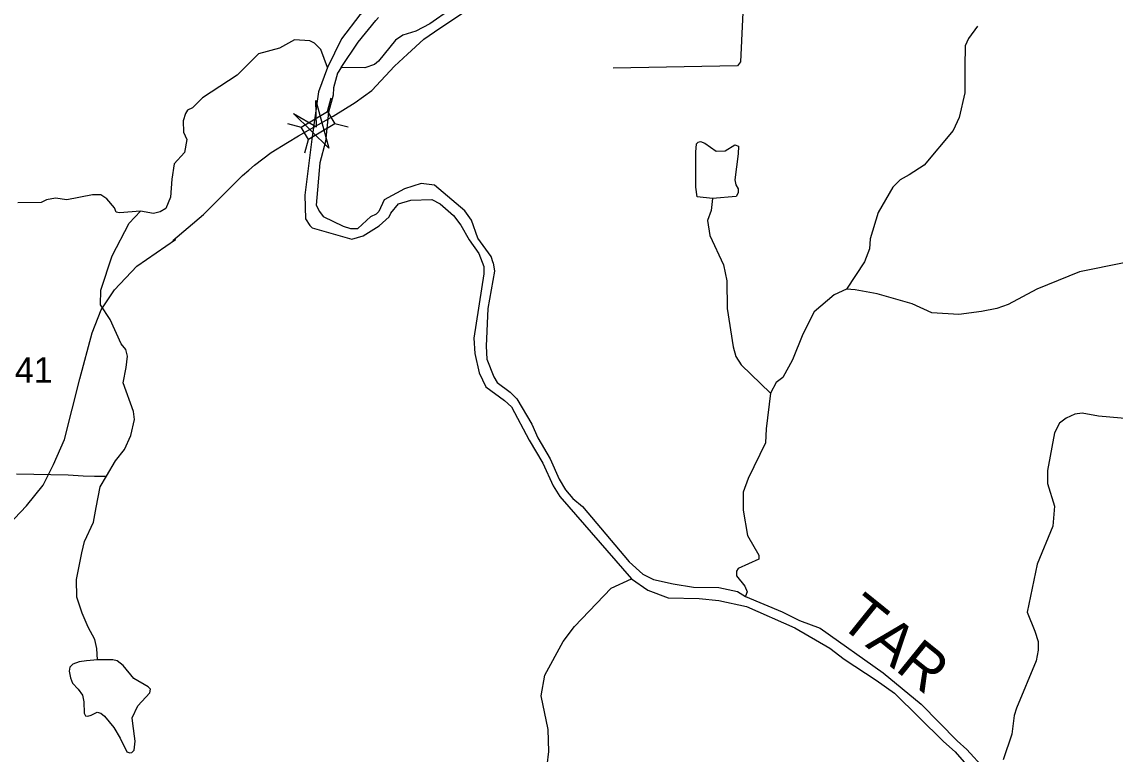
# Model space of a CAD drawing. Extents: x 2056842 to 2160602, y 826753 to 1016856.
# Drawn here: x 2071991 to 2077365, y 928971 to 932569 of the extents above; entities that cross this region are included whole.
import ezdxf

# ---------------------------------------------------------------- set-up
doc = ezdxf.new("R2010")
doc.units = 0
for name, color, linetype in [('Exist Hydrographic Creek Single Shore', 7, 'Continuous'), ('Exist Hydrographic Misc Water Feature', 7, 'Continuous'), ('Exist Hydrographic River Shore', 7, 'Continuous'), ('Exist Hydrographic River Shore Label', 7, 'Continuous'), ('Exist Road Non-System Type 51', 7, 'Continuous'), ('Exist Road Secondary Structure Standard Bridge Attributed CELL', 7, 'Continuous'), ('Exist Road Secondary Structure Standard Bridge CELL', 7, 'Continuous'), ('Exist Road Secondary Type 51 Attributed', 7, 'Continuous'), ('Exist Road Secondary Type 51 Number Label', 7, 'Continuous')]:
    doc.layers.add(name, color=color, linetype=linetype)

msp = doc.modelspace()

# ---------------------------------------------------------------- linework, layer by layer
at = {"layer": 'Exist Hydrographic Creek Single Shore'}
for points in [[(2074401.8, 933902.8), (2074378, 933806.8), (2074366.8, 933574.9), (2074351, 933482.8), (2074345.4, 933390.7), (2074302, 933218.6), (2074272, 933140.5), (2074220.3, 933052.4), (2074200.5, 933000.3), (2074185.1, 932856.3), (2074169.3, 932744.2), (2074139.6, 932676.1), (2074099.8, 932632), (2073996, 932559.7), (2073927.9, 932523.5), (2073864.2, 932503.3), (2073828.3, 932479.2), (2073744.4, 932376.9)], [(2073493.2, 932345.2), (2073461.1, 932432.8), (2073428.9, 932465), (2073406.8, 932476.9), (2073330.8, 932480.8), (2073257.1, 932440.7), (2073155.1, 932412.3), (2073049.3, 932308.1), (2072879.6, 932195.8), (2072829.4, 932147.7), (2072805.5, 932135.7), (2072795.7, 932119.8), (2072783.8, 932083.6), (2072785.9, 932027.8), (2072801.9, 931991.7), (2072790, 931927.6), (2072740, 931871.6), (2072728.2, 931795.7), (2072722.5, 931707.5), (2072698.4, 931651.6), (2072670.5, 931635.4), (2072638.5, 931627.6), (2072574.4, 931639.4)], [(2073744.4, 932376.9), (2073724.5, 932359.2), (2073677, 932344), (2073561.3, 932345.3)], [(2072574.4, 931639.4), (2072470.5, 931631.1), (2072454.5, 931635), (2072446.4, 931655.2), (2072408.3, 931699), (2072378.5, 931718.9), (2072338.5, 931718.8), (2072212.3, 931694.8), (2072156.3, 931702.5), (2072112.5, 931694.6), (2072086.4, 931682.3), (2071970.5, 931680.1)], [(2072406.9, 930337.2), (2072451.6, 930412.8), (2072494.8, 930467.4), (2072526.8, 930537.4), (2072544.5, 930615.4), (2072540.6, 930655.4), (2072488.3, 930795.4), (2072504.1, 930871.4), (2072510, 930927.3), (2072501.8, 930959.4), (2072479.9, 930987.3), (2072425.7, 931107.3), (2072377.5, 931179.1), (2072379.4, 931251.1), (2072435.2, 931419.3), (2072518.8, 931579.4), (2072574.6, 931639.5)], [(2071965.5, 930348.8), (2072219.2, 930342.8), (2072291.7, 930338.5), (2072348, 930337.2), (2072406.9, 930337.2)], [(2072362.1, 929434.2), (2072359.5, 929490.5), (2072349.3, 929534), (2072317.3, 929595.4), (2072287.9, 929663.3), (2072261, 929742), (2072259.8, 929829.1), (2072285.3, 929959.6), (2072299.4, 930015.9), (2072342.9, 930110.7), (2072357, 930182.4), (2072376.2, 930284.8), (2072406.9, 930337.2)]]:
    msp.add_lwpolyline(points, dxfattribs=at)
at = {"layer": 'Exist Hydrographic Misc Water Feature'}
for points in [[(2076687.9, 932548.2), (2076644.1, 932488), (2076628.1, 932452), (2076626.4, 932347.9), (2076626.8, 932220), (2076599.2, 932099.9), (2076569.4, 932035.7), (2076426.1, 931865.3), (2076352.1, 931817.2), (2076308.2, 931793), (2076272.3, 931756.9), (2076200.7, 931632.6), (2076161.2, 931502.5), (2076157.3, 931454.5), (2076133.5, 931390.4), (2076043.9, 931256.1)], [(2075303.8, 931929.8), (2075307.7, 931969.8), (2075315.7, 931977.8), (2075327.6, 931981.9), (2075347.7, 931973.9), (2075403.9, 931934.1), (2075447.8, 931936.3), (2075495.8, 931964.4), (2075513.8, 931958.5), (2075512, 931920.5)], [(2075386.5, 931702.1), (2075310.4, 931709.8), (2075304.5, 931757.8), (2075303.8, 931929.8)], [(2075512, 931920.5), (2075496.2, 931792.4), (2075500.3, 931768.5), (2075512.4, 931748.5), (2075512.6, 931728.5), (2075502.5, 931710.4), (2075386.5, 931702.1)], [(2075386.5, 931702.1), (2075378.7, 931642), (2075360.8, 931594), (2075373.1, 931520), (2075439.6, 931376.2), (2075455.8, 931296.3), (2075458.2, 931160.4), (2075486.9, 930972.4), (2075501.1, 930924.5), (2075527.1, 930884.6), (2075671.5, 930745)], [(2077575, 931521), (2077513.3, 931442.7), (2077473.3, 931410.6), (2077409.3, 931384.5), (2077189.7, 931341.7), (2076979.9, 931255.1), (2076840.1, 931180.7), (2076784.1, 931160.5), (2076708.2, 931146.2), (2076596.3, 931132), (2076464.2, 931139.5), (2076368.1, 931183.1), (2076196, 931232.7), (2076088, 931252.3), (2076043.9, 931256.1)], [(2076043.9, 931256.1), (2075984, 931227.9), (2075886.2, 931143.7), (2075830.6, 931035.5), (2075778.9, 930909.4), (2075731.2, 930821.2), (2075699.4, 930797.1), (2075671.5, 930745)], [(2075671.5, 930745), (2075650.2, 930569), (2075646.3, 930500.9), (2075561, 930324.7), (2075537, 930258.6), (2075537.4, 930170.6), (2075557.7, 930044.7), (2075614.1, 929948.9), (2075614.1, 929928.9), (2075512.2, 929882.6), (2075504.2, 929870.5), (2075504.4, 929846.5), (2075544.6, 929796.7), (2075556.7, 929768.7), (2075548.7, 929746.6)], [(2077579.9, 930605), (2077283.8, 930632.2), (2077203.6, 930645.9), (2077167.8, 930641.8), (2077123.9, 930621.6), (2077091.9, 930597.5), (2077067.9, 930549.4), (2077032.6, 930365.3), (2077032.8, 930301.3), (2077067.1, 930189.5), (2077059.5, 930091.4), (2076982.2, 929905.1), (2076932.8, 929669), (2076971.1, 929575.2), (2076987.3, 929525.2), (2076987.3, 929481.2), (2076977.7, 929429.1), (2076880.3, 929196.9), (2076868.4, 929160.8), (2076856.7, 929068.8), (2076815.1, 928942.7)], [(2074496.1, 928667.5), (2074523.8, 928731.5), (2074533.7, 928785.5), (2074573.4, 928915.7), (2074581.2, 928983.6), (2074578.8, 929091.6), (2074544.3, 929257.6), (2074562, 929359.6), (2074651.4, 929523.9), (2074707.1, 929598), (2074888.6, 929786.6), (2074988.5, 929832.9)], [(2072362.1, 929434.2), (2072309.5, 929429), (2072272.4, 929423.9), (2072241.7, 929412.4), (2072227.6, 929398.3), (2072223.8, 929379.1), (2072230.2, 929345.8), (2072240.4, 929319), (2072267.3, 929289.5), (2072289.1, 929260.1), (2072295.4, 929228.1), (2072296.7, 929173), (2072303.1, 929158.9), (2072314.6, 929157.7), (2072332.5, 929162.8), (2072362, 929176.9), (2072379.9, 929173), (2072397.8, 929157.7), (2072443.8, 929101.3), (2072474.5, 929048.9), (2072506.5, 928982.3), (2072521.9, 928977.2), (2072532.1, 928979.7), (2072543.6, 928991.3), (2072547.5, 929034.8), (2072536, 929121.8), (2072533.4, 929148.7), (2072561.5, 929207.6), (2072620.4, 929272.9), (2072624.2, 929290.8), (2072611.4, 929301), (2072542.3, 929343.3), (2072488.6, 929406), (2072459.2, 929430.3), (2072438.7, 929434.2), (2072362.1, 929434.2)]]:
    msp.add_lwpolyline(points, dxfattribs=at)
at = {"layer": 'Exist Hydrographic River Shore'}
for points in [[(2073743.6, 932682.9), (2073705.7, 932655.9), (2073680, 932621.2), (2073652.6, 932603.7), (2073562.9, 932485.3), (2073493.2, 932345.2)], [(2073561.3, 932345.1), (2073644.9, 932469.4), (2073731.5, 932576), (2073744.9, 932590.4)], [(2073493.2, 932345.2), (2073449.6, 932225.1), (2073415.9, 931993), (2073382.5, 931717), (2073384.6, 931600.9), (2073406.7, 931569), (2073418.8, 931557), (2073612.8, 931501.4), (2073669, 931517.5), (2073747.1, 931567)], [(2073561.3, 932345.1), (2073543.3, 932316.9), (2073523.4, 932245.2), (2073521.4, 932209.1), (2073497.7, 932124.9), (2073483.8, 931980.8), (2073456.1, 931877.1), (2073438.3, 931669.1), (2073454.4, 931636.9), (2073472.6, 931612.9), (2073570.7, 931565.3), (2073606.6, 931553.4), (2073642.6, 931553.3), (2073706.6, 931613.3), (2073734.4, 931625.5), (2073746.4, 931637.4)], [(2074307.6, 931384.6), (2074297.4, 931416.6), (2074233, 931506.2), (2074200.7, 931594.2), (2074168.8, 931640.1), (2074020.2, 931767.6), (2073954.4, 931775.5), (2073872.5, 931749), (2073772.6, 931695), (2073746.4, 931637.4)], [(2073747.1, 931567), (2073796.9, 931611.1), (2073804.9, 931629.1), (2073842.8, 931675.3), (2073902.7, 931693.4), (2074006.7, 931695.8), (2074046.7, 931675.9), (2074112.9, 931618.1), (2074149, 931570.2), (2074189.2, 931498.3), (2074237.6, 931430.4), (2074261.6, 931366.6), (2074261.8, 931330.6)], [(2074307.6, 931384.6), (2074313.6, 931344.4), (2074282.2, 931160.3), (2074272.8, 930976.5), (2074276.8, 930912.4), (2074311, 930824.7), (2074327.2, 930796.5), (2074391.5, 930748.9), (2074423.7, 930717.1), (2074497.9, 930593.1), (2074528, 930525.2), (2074588.5, 930421.6), (2074632.7, 930321.6), (2074662.8, 930269.8), (2074699, 930227.7), (2074747, 930188), (2074976, 929916.8), (2075044.3, 929855), (2075096.3, 929829), (2075192.3, 929807.3), (2075292.4, 929791.7), (2075416.4, 929790.2), (2075508.5, 929770.5), (2075548.4, 929746.4)], [(2074261.8, 931330.6), (2074212.8, 931014.4), (2074217.1, 930940.5), (2074239.2, 930844.5), (2074271.4, 930776.6), (2074363.7, 930708.9), (2074397.9, 930677.1), (2074484.5, 930513.2), (2074552.5, 930401.5), (2074603, 930289.7), (2074635.2, 930237.7), (2074988.5, 929832.9)], [(2074988.5, 929832.9), (2075068.6, 929777.2), (2075168.7, 929739.5), (2075320.7, 929736), (2075416.8, 929726.2), (2075553, 929696.7), (2075791, 929591.4), (2075963.3, 929492), (2076033.6, 929438.2), (2076189.9, 929334.7), (2076280.1, 929271), (2076520.8, 929033.8), (2076579.1, 928982), (2076635.2, 928918.1), (2076763.6, 928806.6), (2076881.7, 928740.9), (2076909.8, 928733.1)], [(2075548.4, 929746.4), (2075728.6, 929671.1), (2075813, 929627.4), (2075914.9, 929589.8), (2076225.7, 929370.8), (2076412.2, 929217.3), (2076588.6, 929035.8), (2076636.9, 928994.1), (2076723.2, 928898.1), (2076767.3, 928858.5)]]:
    msp.add_lwpolyline(points, dxfattribs=at)
at = {"layer": 'Exist Road Non-System Type 51'}
msp.add_lwpolyline([(2075554.8, 933033.2), (2075522.9, 932373.2), (2075508.8, 932353.1), (2074896.9, 932341.2)], dxfattribs=at)
at = {"layer": 'Exist Road Secondary Structure Standard Bridge Attributed CELL'}
msp.add_lwpolyline([(2073435.4, 932183.5), (2073500.6, 931948.6), (2073326.7, 932119.5), (2073438.7, 932053.6)], close=True, dxfattribs=at)
at = {"layer": 'Exist Road Secondary Structure Standard Bridge CELL'}
for p, q in [((2073493.9, 932129.3), (2073511, 932196.1)), ((2073296.8, 932069.7), (2073363.7, 932052.6)), ((2073529, 932069.9), (2073595.8, 932052.8)), ((2073382.5, 931925), (2073399.6, 931991.9))]:
    msp.add_line(p, q, dxfattribs=at)
msp.add_lwpolyline([(2073363.7, 932052.6), (2073493.7, 932129.6), (2073529.7, 932068.8), (2073399.6, 931991.9)], close=True, dxfattribs=at)
at = {"layer": 'Exist Road Secondary Type 51 Attributed'}
for points in [[(2073449, 932064.6), (2073520.8, 932106.2), (2073629.1, 932173), (2073712.1, 932232.1), (2073822.8, 932351), (2073886.3, 932411.3), (2073966.4, 932484.3), (2074045, 932538.8), (2074152.5, 932608.2), (2074221.2, 932646), (2074397.3, 932738.7), (2074667.5, 932858.2), (2074951.2, 932922.9), (2075290.6, 932985.8), (2075568.9, 933043.3), (2075853.5, 933096.3), (2076016.9, 933141.2), (2076403, 933270.6), (2076818.7, 933420.6), (2077075.4, 933515.9), (2077170.6, 933551.8), (2077210.8, 933592)], [(2071341.1, 929545.7), (2071482.1, 929681.4), (2071738.9, 929916.7), (2071924.7, 930097.3), (2072014.5, 930190.8), (2072095.3, 930293.2), (2072147.4, 930393.8), (2072200.3, 930516.9), (2072275.8, 930815.2), (2072336.8, 931041.6), (2072381.7, 931154.8), (2072447.2, 931252.7), (2072556.8, 931369.5), (2072745.9, 931499.8), (2072732.7, 931495.3), (2072883.6, 931622.9), (2073075.6, 931813.7), (2073106.3, 931840.2), (2073135.2, 931865.4), (2073217.1, 931927.2), (2073296.5, 931976.4), (2073350.7, 932009.1), (2073449, 932064.6)]]:
    msp.add_lwpolyline(points, dxfattribs=at)

# ---------------------------------------------------------------- texts
at = {"layer": 'Exist Hydrographic River Shore Label'}
msp.add_text('TAR', height=210, rotation=321.1057, dxfattribs=at).set_placement((2075999.9, 929611.2))
at = {"layer": 'Exist Road Secondary Type 51 Number Label'}
msp.add_text('1141', height=125, dxfattribs=at).set_placement((2071770.9, 930796.7))

doc.saveas('drawing.dxf')
